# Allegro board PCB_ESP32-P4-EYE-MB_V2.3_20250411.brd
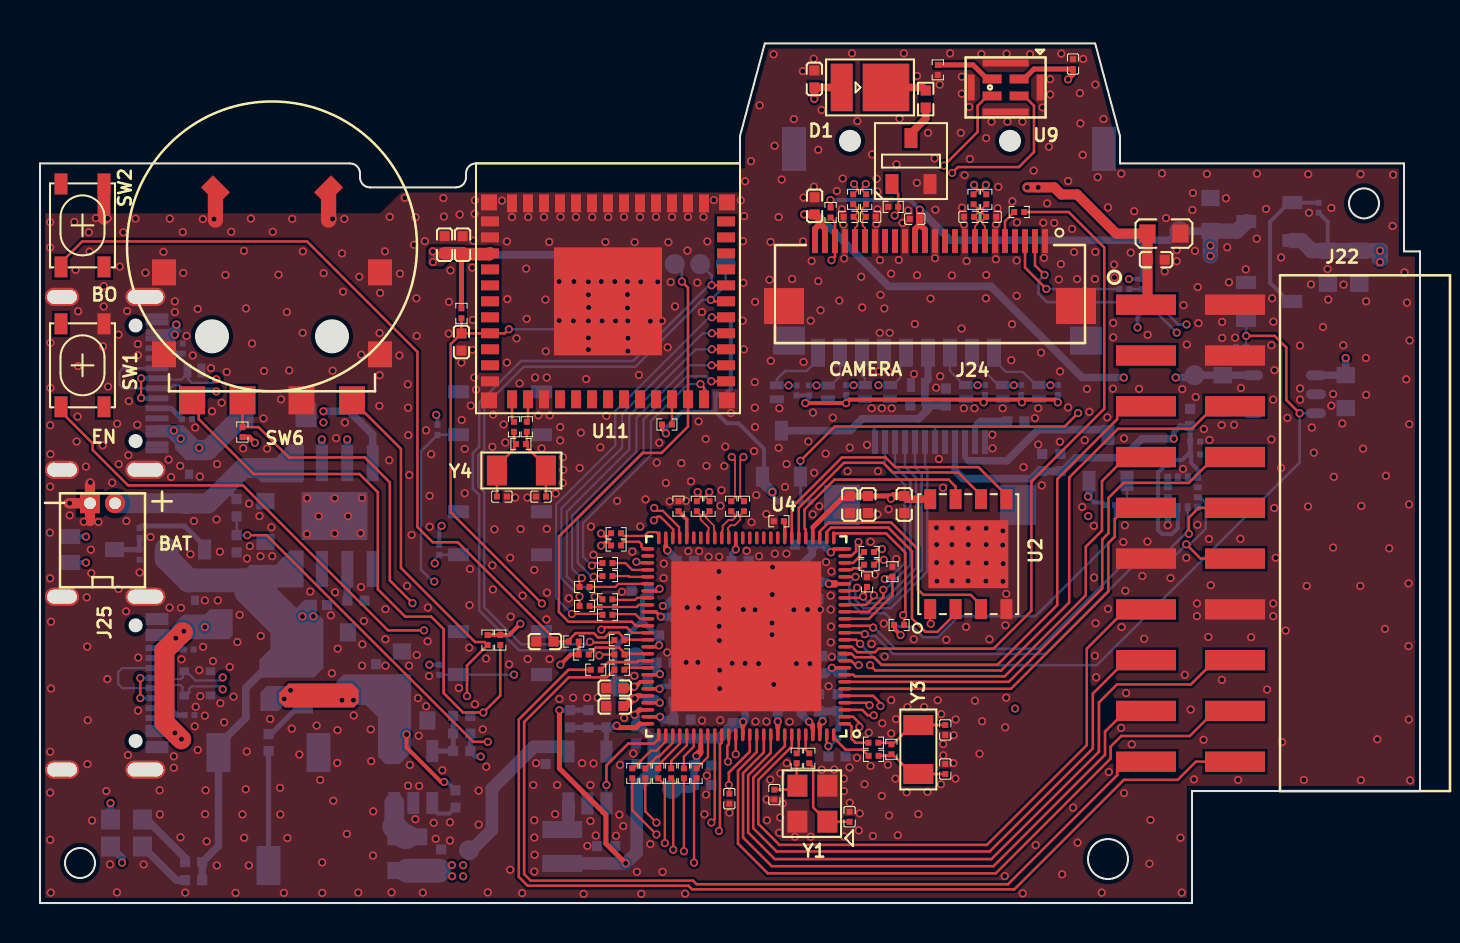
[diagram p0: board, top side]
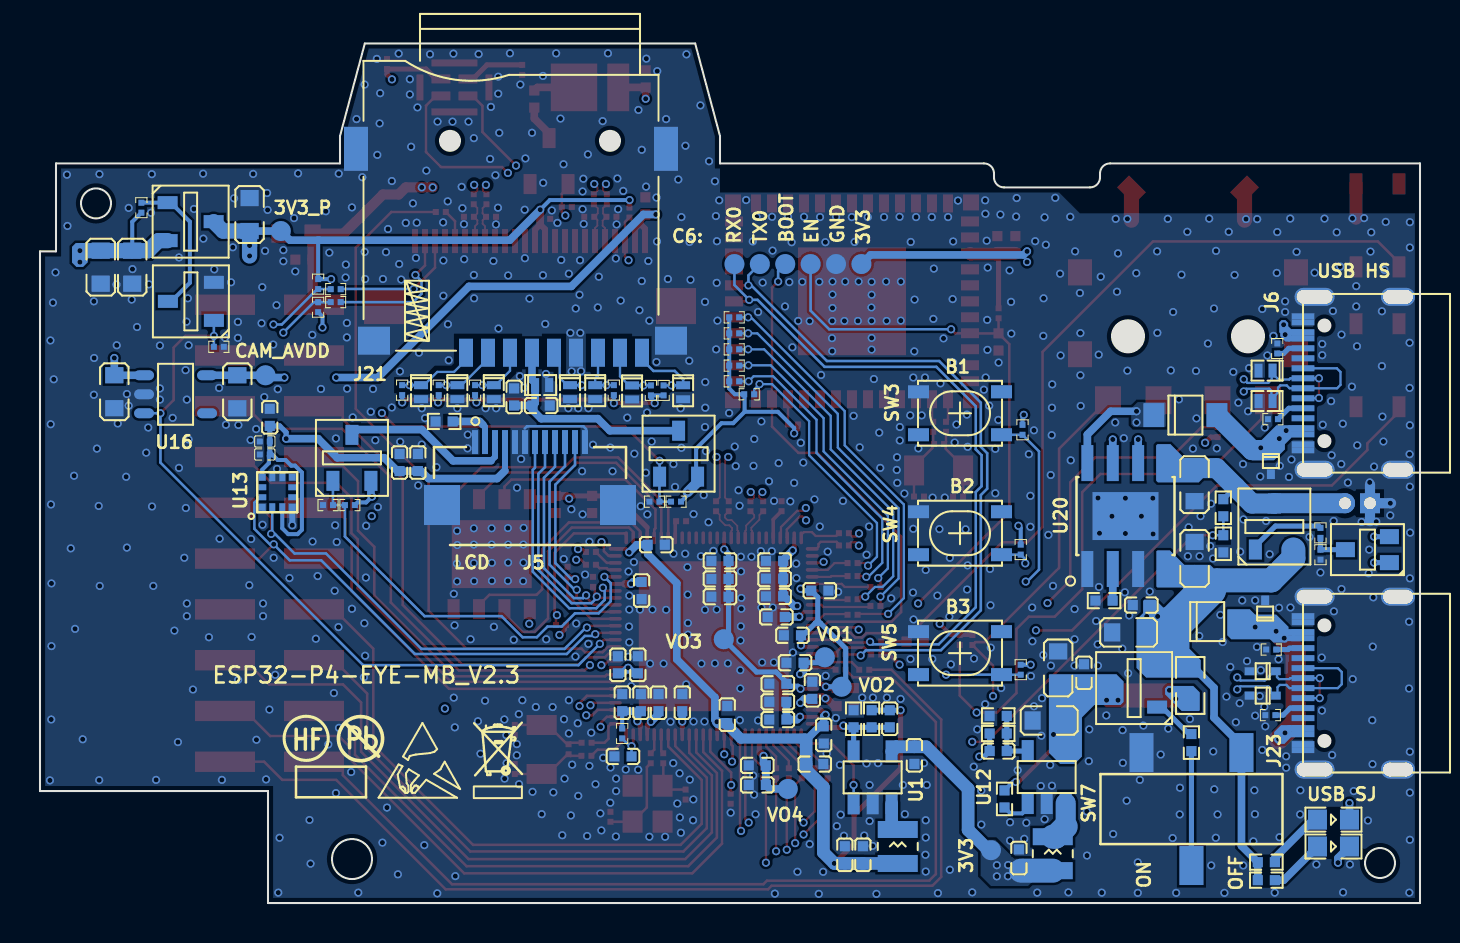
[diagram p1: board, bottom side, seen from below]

Outline 69 x 43 mm; copper layers: TOP, L2_GND1, L3_SIGNAL, L4_GND2, L5_POWER, BOTTOM. Coordinates in mm from the lower left corner of the outline.
Outline path: circle c2,2 r0.75 ; circle c2.5,20 r0.25 ; circle c3.75,20 r0.25 ; circle c4.78,28.89 r0.3 ; circle c4.78,23.11 r0.3 ; circle c4.78,13.89 r0.3 ; circle c4.78,8.11 r0.3 ; circle c8.6,28.35 r0.8 ; circle c14.6,28.35 r0.8 ; circle c40.5,38.13 r0.5 ; circle c48.5,38.13 r0.5 ; circle c53.4,2.2 r1 ; circle c66.2,35 r0.75 ; 0,37 0,0 57.6,0 57.6,5.6 69,5.6 69,32.6 68.2,32.6 68.2,37 54,37 54,38.37 52.76,43 36.24,43 35,38.37 35,37 21.8,37 arc(21.45,36.85) 21.3,36.5 21.3,36.3 arc(21.15,35.95) 20.8,35.8 16.5,35.8 arc(16.15,35.95) 16,36.3 16,36.5 arc(15.85,36.85) 15.5,37 0,37 ; 0.7,30.02 arc(0.4,30.32) 0.7,30.62 1.5,30.62 arc(1.8,30.32) 1.5,30.02 0.7,30.02 ; 0.7,21.38 arc(0.4,21.68) 0.7,21.98 1.5,21.98 arc(1.8,21.68) 1.5,21.38 0.7,21.38 ; 0.7,15.03 arc(0.4,15.32) 0.7,15.62 1.5,15.62 arc(1.8,15.32) 1.5,15.03 0.7,15.03 ; 0.7,6.38 arc(0.4,6.67) 0.7,6.97 1.5,6.97 arc(1.8,6.67) 1.5,6.38 0.7,6.38 ; 4.72,30.02 arc(4.42,30.32) 4.72,30.62 5.82,30.62 arc(6.12,30.32) 5.82,30.02 4.72,30.02 ; 4.72,21.38 arc(4.42,21.68) 4.72,21.98 5.82,21.98 arc(6.12,21.68) 5.82,21.38 4.72,21.38 ; 4.72,15.03 arc(4.42,15.32) 4.72,15.62 5.82,15.62 arc(6.12,15.32) 5.82,15.03 4.72,15.03 ; 4.72,6.38 arc(4.42,6.67) 4.72,6.97 5.82,6.97 arc(6.12,6.67) 5.82,6.38 4.72,6.38

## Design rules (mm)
net group CAM_C: nets CAM_CN CAM_CP
net group CAM_D: nets CAM_DN CAM_DP
net group CSI_CLKN: nets CSI_CLKN CSI_CLKN_A
net group CSI_CLKP: nets CSI_CLKP CSI_CLKP_A
net group CSI_DATA0N: nets CSI_DATA0N CSI_DATA0N_A
net group CSI_DATA0P: nets CSI_DATA0P CSI_DATA0P_A
net group GPIO24: nets GPIO24 USB_SJ_DN
net group GPIO25: nets GPIO25 USB_SJ_DP
net group GPIO27: nets GPIO27 SD2_CMD
net group GPIO28: nets GPIO28 SD2_CLK
net group GPIO29: nets GPIO29 SD2_D0
net group GPIO30: nets GPIO30 SD2_D1
net group GPIO31: nets GPIO31 SD2_D2
net group GPIO32: nets GPIO32 SD2_D3
net group GPIO39: nets GPIO39 SD1_D0
net group GPIO40: nets GPIO40 SD1_D1
net group GPIO41: nets GPIO41 SD1_D2
net group GPIO42: nets GPIO42 SD1_D3
net group GPIO43: nets GPIO43 SD1_CLK
net group GPIO44: nets GPIO44 SD1_CMD
net group USB2: nets USB_DM USB_DP

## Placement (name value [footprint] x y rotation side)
C1  22pF/50V(5%)  [C0201]  40.48 4.31 90 top
C2  1uF/10V(10%)  [C0402]  39.85 7.33 180 bottom
C3  0.1uF/10V(10%)(NC)  [C0402]  25.25 13.08 180 top
C4  22pF/50V(5%)  [C0201]  36.72 5.42 270 top
C5  0.1uF/10V(10%)  [C0402]  43.21 19.94 270 top
C6  4.7uF/6.3V(20%)  [C0402]  25.28 7.39 270 bottom
C7  22pF/50V(5%)(NC)  [C0402]  26.51 9.22 270 bottom
C8  10uF/6.3V(20%)  [C0402]  27.86 2.41 90 bottom
C18  22pF/50V(5%)  [C0201]  45.26 8.66 270 top
C19  22pF/50V(5%)  [C0201]  45.26 6.7 90 top
C20  1uF/10V(10%)  [C0402]  41.39 19.94 270 top
C25  0.1uF/10V(10%)  [C0402]  40.49 19.94 270 top
C47  10uF/6.3V(20%)  [C0402]  38.73 34.88 90 top
C48  0.1uF/10V(10%)  [C0201]  43.74 34.23 180 top
C50  1uF/10V(10%)  [C0402]  28.74 10.75 180 top
C51  1uF/10V(10%)  [C0402]  28.74 9.85 180 top
C52  0.1uF/10V(10%)  [C0402]  38.72 41.23 90 top
C53  10nF/10V(10%)  [C0201]  57.76 22.44 0 bottom
C55  1uF/10V(10%)  [C0402]  32.11 10.97 0 bottom
C56  1uF/10V(10%)  [C0402]  31.25 12.02 0 bottom
C82  10uF/6.3V(20%)  [C0402]  39.89 10.02 90 bottom
C83  0.1uF/10V(10%)  [C0402]  40.11 11.92 90 bottom
C84  0.1uF/10V(10%)  [C0402]  38.96 10.02 90 bottom
C85  0.1uF/10V(10%)  [C0402]  38.07 10.02 90 bottom
C86  0.1uF/10V(10%)  [C0402]  38.19 17.92 180 bottom
C87  10uF/6.3V(20%)  [C0402]  39.11 11.92 90 bottom
C88  0.1uF/10V(10%)  [C0402]  38.92 15.63 270 bottom
C89  10uF/6.3V(20%)  [C0402]  30.26 6.95 180 bottom
C90  0.1uF/10V(10%)  [C0402]  36.89 10.02 90 bottom
C91  1uF/10V(10%)  [C0402]  35 15.32 0 bottom
C92  0.1uF/10V(10%)  [C0402]  35 16.21 0 bottom
C93  10nF/50V(10%)  [C0402]  35 17.11 0 bottom
C94  0.1uF/10V(10%)  [C0402]  34.64 9.42 90 bottom
C95  10uF/6.3V(20%)  [C0402]  32.11 10.07 0 bottom
C96  0.1uF/10V(10%)  [C0402]  32.11 9.18 0 bottom
C97  0.1uF/10V(10%)  [C0402]  32.18 14.31 0 bottom
C98  4.7uF/6.3V(20%)  [C0402]  32.27 15.34 0 bottom
C99  0.1uF/10V(10%)  [C0402]  32.27 16.23 0 bottom
C100  10nF/50V(10%)  [C0402]  32.27 17.12 0 bottom
C101  0.1uF/10V(10%)  [C0402]  33.14 6.89 0 bottom
C102  10uF/6.3V(20%)  [C0402]  33.14 5.91 0 bottom
C103  0.1uF/10V(10%)  [C0402]  30.38 10.64 90 bottom
C104  1uF/10V(10%)  [C0402]  31.38 13.39 0 bottom
C105  0.1uF/10V(10%)  [C0402]  30.01 15.63 180 bottom
C107  0.1uF/10V(10%)  [C0402]  29.81 8.41 270 bottom
C109  10uF/6.3V(20%)  [C0402]  20.23 32.93 90 top
C110  0.1uF/10V(10%)  [C0402]  21.13 32.93 90 top
C111  0.1uF/10V(10%)  [C0402]  21.07 28.07 270 top
C113  10uF/10V(20%)  [C0603]  18.09 11.76 90 bottom
C114  0.1uF/10V(10%)  [C0402]  16.8 11.52 90 bottom
C118  10uF/10V(20%)  [C0603]  14.57 13.54 0 bottom
C119  0.1uF/10V(10%)  [C0402]  13.93 14.9 0 bottom
C120  10uF/10V(20%)  [C0603]  18.54 9.13 0 bottom
C121  22pF/50V(5%)(NC)  [C0402]  21.09 7.6 180 bottom
C122  10uF/6.3V(20%)  [C0402]  20.06 2.25 90 bottom
C138  10uF/10V(20%)  [C0603]  65.28 25.58 270 bottom
C141  10uF/10V(20%)  [C0603]  59.13 25.58 270 bottom
C148  10uF/6.3V(20%)  [C0402]  45.3 25.32 90 bottom
C149  0.1uF/10V(10%)  [C0402]  43.94 24.89 180 bottom
C150  10uF/6.3V(20%)(NC)  [C0402]  51.02 22.04 90 bottom
C151  0.1uF/10V(10%)  [C0402]  50.11 22.04 90 bottom
C152  0.1uF/10V(10%)  [C0201]  51.65 41.97 90 top
C160  0.1uF/10V(10%)  [C0402]  55.8 32.18 0 top
C161  10uF/10V(20%)  [C0603]  56.2 33.49 0 top
C163  TBD  [C0201]  47.55 34.33 0 top
C164  TBD  [C0201]  46.45 34.33 180 top
C165  TBD  [C0201]  41.54 34.33 0 top
C166  TBD  [C0201]  40.43 34.33 180 top
C168  22uF/10V(20%)  [C0603]  11.27 20.93 90 bottom
C169  10uF/10V(20%)  [C0603]  11.27 17.24 270 bottom
C170  22pF/50V(5%)  [C0201]  23.09 20.33 0 top
C171  22pF/50V(5%)  [C0201]  25.05 20.33 180 top
C172  0.1uF/10V(10%)(NC)  [C0201]  34.47 5.22 270 top
C173  10uF/6.3V(20%)  [C0402]  28.76 2.41 90 bottom
C174  10uF/10V(20%)  [C0603]  64.39 31.81 270 bottom
C175  10uF/10V(20%)(NC)  [C0603]  58.52 34.44 90 bottom
C176  0.1uF/10V(10%)  [C0201]  57.76 23.09 0 bottom
C177  2.2uF/10V(20%)  [C0402]  57.51 24.3 90 bottom
C178  10uF/10V(20%)  [C0603]  65.96 31.81 270 bottom
D1  WHITE LED  [LED2835]  41.5 40.8 0 top
D3  LESD8D3.3CAT5G  [SOD882]  43.89 25.91 0 bottom
D4  LESD8D3.3CAT5G  [SOD882]  46.31 25.56 90 bottom
D5  GREEN LED  [LED0603]  4.33 4.17 0 bottom
D6  LESD8D3.3CAT5G  [SOD882]  42.5 25.56 90 bottom
D7  LESD8D3.3CAT5G  [SOD882]  48.13 25.56 90 bottom
D8  LESD8D3.3CAT5G  [SOD882]  49.95 25.56 90 bottom
D10  LESD8D3.3CAT5G  [SOD882]  39.4 25.54 90 bottom
D11  LESD8D3.3CAT5G  [SOD882]  41.24 25.56 90 bottom
D12  DSS24  [SOD123FL]  11.73 24.41 180 bottom
D15  LESD5D5.0CT1G  [SOD523]  7.45 22.11 90 bottom
D16  LESD5D5.0CT1G  [SOD523]  7.87 11.6 180 bottom
D17  LESD5D5.0CT1G  [SOD523]  7.87 10.38 180 bottom
D18  DSS24  [SOD123FL]  10.64 14.08 180 bottom
D19  LESD5D5.0CT1G  [SOD523]  7.74 14.48 270 bottom
D20  ESD7951ST5G  [SOD882]  7.72 26.64 180 bottom
D21  ESD7951ST5G  [SOD882]  7.72 25.11 180 bottom
D22  LESD8D3.3CAT5G  [SOD882]  36.84 25.55 90 bottom
D23  BAT54CW  [SOT323]  2.63 17.68 0 bottom
D25  RED LED  [LED0603]  4.33 2.83 0 bottom
J5  FFC12-0P5-LCD  [FFC12_0P5_AFC24-S12FIC-00]  44.5 23.06 180 bottom
J6  -  [USB_TYPEC_16P_F]  4.78 26 90 bottom
J21  TF_CARD  [TF_CARDA]  45.45 38.13 90 bottom
J22  CON10X2  [CON10X2_2P54_SMT_R]  56.77 18.5 270 top
J23  -  [USB_TYPEC_16P_F]  4.78 11 90 bottom
J24  FPC_24P  [FFC24_0P5_FPC-05FB-24PH20]  44.5 33.11 0 top
J25  CON2X1_1P25  [GH2_1P25_R]  3.12 20 0 top
L1  2.2uH(20%)_2A  [L2520]  26.11 2.83 270 bottom
L5  2.2uH(20%)_2A  [L2520]  18.36 2.47 270 bottom
Q1  LBSS138LT1G  [SOT23-3]  61.46 30.1 0 bottom
Q2  AO3401A  [SOT23-3]  53.4 22.27 90 bottom
Q4  SI2302  [SOT23-3]  43.55 37.12 90 top
Q6  AO3401A  [SOT23-3]  7.28 18.83 90 bottom
Q8  AO3401A  [SOT23-3]  37.07 22.48 90 bottom
Q9  AO3401A  [SOT23-3]  14.29 10.75 0 bottom
Q10  AO3401A  [SOT23-3]  61.47 34.09 180 bottom
R1  0(1%)  [R0201]  38.46 7.24 270 top
R2  10K(1%)  [R0201]  39.89 8.48 90 bottom
R3  10K(1%)  [R0201]  27.19 12.43 0 top
R4  10K(1%)  [R0201]  26.69 13.08 0 top
R5  0(1%)  [R0201]  37.83 7.24 270 top
R7  10K(1%)  [R0201]  42.95 13.91 180 top
R8  499K(1%)(NC)  [R0402]  27.42 9.22 270 bottom
R9  499K(1%)(NC)  [R0402]  28.32 9.22 90 bottom
R10  2K(1%)  [R0402]  15.8 15.13 0 bottom
R15  1M(1%)  [R0402]  9.83 19.77 90 bottom
R16  332K(1%)  [R0402]  9.83 17.97 270 bottom
R17  51K(1%)  [R0201]  47.25 25.66 90 bottom
R23  0(1%)  [R0201]  41.45 17.56 0 top
R24  0(1%)  [R0201]  47.31 35.2 90 top
R25  0(1%)  [R0201]  46.68 35.2 90 top
R26  0(1%)  [R0201]  40.66 35.2 90 top
R27  0(1%)  [R0201]  41.31 35.2 90 top
R58  10M(1%)(NC)  [R0201]  42.57 7.69 90 top
R59  0(1%)  [R0201]  41.67 8.02 0 top
R61  0(1%)  [R0201]  41.68 7.36 0 top
R67  10K(1%)  [R0201]  39.53 34.54 270 top
R72  3.9(1%)  [R0402]  44.28 40.22 270 top
R73  10K(1%)  [R0201]  42.66 34.83 180 top
R79  10K(1%)(NC)  [R0201]  54.6 19.91 0 bottom
R102  0(1%)  [R0201]  32.83 6.49 270 top
R103  0(1%)  [R0201]  32.19 6.49 270 top
R104  33(1%)  [R0201]  28.8 18.5 180 top
R105  33(1%)  [R0201]  28.8 17.89 180 top
R107  0(1%)  [R0201]  31.56 6.49 270 top
R108  0(1%)  [R0201]  30.91 6.49 270 top
R110  0(1%)  [R0201]  30.26 6.49 270 top
R118  0(1%)  [R0201]  28.97 11.67 180 top
R122  0(1%)  [R0201]  29.62 6.49 270 top
R128  51K(1%)  [R0201]  34.29 29.3 180 bottom
R129  51K(1%)  [R0201]  34.29 28.5 180 bottom
R130  51K(1%)  [R0201]  34.29 27.7 180 bottom
R131  51K(1%)  [R0201]  34.29 26.89 180 bottom
R132  51K(1%)  [R0201]  34.29 26.1 180 bottom
R133  51K(1%)  [R0201]  33.54 25.45 180 bottom
R134  100K(1%)  [R0201]  21.07 29.5 90 top
R135  10K(1%)  [R0201]  31.35 23.94 180 top
R142  5.1K(1%)  [R0201]  7.35 24.21 180 bottom
R143  5.1K(1%)  [R0201]  7.14 27.74 270 bottom
R145  10K(1%)  [R0402]  20.77 5.21 270 bottom
R146  100K(1%)  [R0402]  21.09 8.48 180 bottom
R148  22.1K(1%)  [R0402]  21.09 9.36 0 bottom
R202  4.02K(1%)  [R0201]  36.94 19.1 180 top
R203  4.02K(1%)  [R0201]  31.92 19.85 90 top
R230  10K(1%)  [R0201]  63.93 34.79 270 bottom
R231  51K(1%)  [R0201]  49.06 25.66 90 bottom
R232  51K(1%)  [R0201]  40.31 25.66 90 bottom
R233  51K(1%)  [R0201]  38.45 25.65 90 bottom
R234  51K(1%)  [R0201]  50.89 25.66 90 bottom
R238  10K(1%)(NC)  [R0201]  42.62 16.57 90 top
R241  10K(1%)(NC)  [R0201]  41.35 16.07 90 top
R243  10(1%)  [R0402]  48.79 24.09 0 bottom
R246  10K(1%)  [R0201]  44.89 41.68 90 top
R250  0(1%)  [R0201]  28.97 12.43 180 top
R255  0(1%)  [R0201]  41.45 16.93 0 top
R259  0(1%)  [R0201]  27.79 11.67 180 top
R262  10K(1%)  [R0201]  19.88 23.67 90 bottom
R263  10K(1%)  [R0201]  19.96 17.68 90 bottom
R264  10K(1%)  [R0201]  19.96 11.67 90 bottom
R268  5.1K(1%)  [R0201]  7.48 9.4 180 bottom
R269  5.1K(1%)  [R0201]  7.44 12.68 180 bottom
R272  2.2K(1%)  [R0201]  55.09 29.81 270 bottom
R273  2.2K(1%)  [R0201]  55.09 30.96 90 bottom
R274  0(1%)  [R0201]  27.23 14.86 180 top
R275  0(1%)  [R0201]  28.37 15.19 180 top
R276  0(1%)  [R0201]  27.23 15.81 180 top
R277  0(1%)  [R0201]  28.37 16.36 180 top
R278  0(1%)  [R0201]  28.37 17.01 180 top
R279  0(1%)  [R0201]  28.37 14.42 180 top
R280  51K(1%)  [R0201]  37.82 25.65 90 bottom
R283  0(1%)  [R0201]  32.84 19.85 90 top
R284  0(1%)  [R0201]  33.48 19.85 90 top
R285  0(1%)  [R0201]  34.56 19.85 90 top
R286  0(1%)  [R0201]  35.2 19.85 90 top
R288  100K(1%)  [R0201]  4.98 17.42 270 bottom
R289  100K(1%)  [R0201]  4.98 18.52 90 bottom
R290  5.1K(1%)  [R0402]  7.68 1.14 0 bottom
R291  5.1K(1%)  [R0402]  7.68 2.04 0 bottom
R292  10K(1%)  [R0201]  23.01 13.16 90 top
R293  10K(1%)  [R0201]  22.38 13.16 90 top
R295  10K(1%)  [R0201]  10.12 23.56 270 top
R297  10M(1%)(NC)  [R0201]  24.05 22.96 0 top
R298  0(1%)  [R0201]  23.7 23.82 270 top
R299  0(1%)  [R0201]  24.34 23.83 270 top
R300  0(1%)  [R0201]  28.97 13.16 180 top
R302  0(1%)  [R0201]  54.22 30.06 0 bottom
R303  0(1%)  [R0201]  54.22 30.71 0 bottom
R304  0(1%)  [R0201]  48.96 34.57 180 top
R306  10K(1%)  [R0201]  53.51 19.91 0 bottom
R307  100K(1%)  [R0402]  11.43 8.03 270 bottom
R308  10K(1%)(NC)  [R0201]  38.28 20.08 180 bottom
R309  10K(1%)  [R0201]  37.2 20.08 180 bottom
R310  10K(1%)(NC)  [R0201]  60.06 27.83 0 bottom
R311  0(1%)(NC)  [R0603]  11.49 10.88 90 bottom
SW1  SW_SP_4P  [SW4-4P2X3P2X2P5-SMT]  2.12 26.9 270 top
SW2  SW_SP_4P  [SW4-4P2X3P2X2P5-SMT]  2.12 33.9 270 top
SW3  SW_SP_4P  [SW4-4P2X3P2X2P5-SMT]  23 24.5 180 bottom
SW4  SW_SP_4P  [SW4-4P2X3P2X2P5-SMT]  23 18.5 180 bottom
SW5  SW_SP_4P  [SW4-4P2X3P2X2P5-SMT]  23 12.5 180 bottom
SW6  -  [SIQ-02FVS3]  11.6 32.85 0 top
SW7  K3-1235S-F1  [SW3-9P1X3P5X5P5-SMT]  11.43 4.7 180 bottom
TP24  TESTPOINT  [TPC1]  28.92 10.82 180 bottom
TP25  TESTPOINT  [TPC1]  31.61 5.71 180 bottom
TP26  TESTPOINT  [TPC1]  29.76 12.29 180 bottom
TP27  TESTPOINT  [TPC1]  34.81 13.2 180 bottom
TP44  TESTPOINT  [TPC1]  30.47 31.97 0 bottom
TP45  TESTPOINT  [TPC1]  31.74 31.97 0 bottom
TP46  TESTPOINT  [TPC1]  34.28 31.97 90 bottom
TP47  TESTPOINT  [TPC1]  33.01 31.97 90 bottom
TP48  TESTPOINT  [TPC1]  29.2 31.97 90 bottom
TP49  TESTPOINT  [TPC1]  21.45 2.64 0 bottom
TP51  TESTPOINT  [TPC1]  57.72 26.4 0 bottom
TP52  TESTPOINT  [TPC1]  56.96 33.62 270 bottom
TP53  TESTPOINT  [TPC1]  27.93 31.97 180 bottom
U1  TLV62569  [SOT23_0P95_2P6]  27.37 6.28 90 bottom
U2  FLASH  [WSON8_1P27_6X5_E4X3P4]  46.41 17.45 90 top
U4  ESP32-P4  [QFN104_0P35_10_E7P5_A]  35.31 13.34 180 top
U9  MSM261D  [OCLGA-8]  48.28 40.8 90 top
U11  -  [ESP32-C6-MINI-1U]  21.8 24.5 0 top
U12  TLV62569  [SOT23_0P95_2P6]  18.67 6.3 90 bottom
U13  QMA6100P  [LGA12_0P5_2]  57.14 20.55 90 bottom
U16  ME6211C33M5G-N  [SOT23-5]  62.22 25.45 180 bottom
U20  AP5056  [SOP8_1P27_4P9X3P9_E3P3X2P4]  14.73 19.36 90 bottom
Y1  40MHz  [XTAL3225]  38.62 4.97 90 top
Y3  32.768KHz  [XTAL3215_2P]  43.92 7.68 270 top
Y4  32.768KHz  [XTAL3215_2P]  24.07 21.64 180 top

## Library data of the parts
C1-C5 C7 C18 C19 C25 C47 C48 C50-C53 C55 C56 C83-C86 C88 C90 C92 C94 C96 C97 C99 C101 C103 C105 C107 C109-C111 C113 C114 C118 C119 C121 C138 C141 C148-C151 C160 C161 C163-C166 C170-C172 C174-C178 = CAPACITOR
C6 C8 C20 C82 C87 C89 C91 C93 C95 C98 C100 C102 C104 C120 C122 C173 = CAP
C152 C168 C169 = CAP NP
D1 = DIODE_LIGHT
D3 D4 D6-D8 D10 D11 D15-D17 D19-D22 = DIODE_BI_DIR
D5 D25 = LED_1
D12 D18 = DIODE_S
D23 = BAT54C_0
J5 = FFC12-0P5-LCD_3
J6 J23 = USB_TYPEC_16P_F
J21 = TF_SD_SOCKET
J22 = CON10X2
J24 = FPC_24P
J25 = CON2X1
L1 L5 = INDUCTOR
Q1 = MOSFET_EN_DGS_0
Q2 Q8 Q10 = PMOS
Q4 = NMOS
Q6 Q9 = PMOS_0
R1-R5 R7-R9 R17 R23-R27 R58 R59 R61 R67 R72 R73 R79 R118 R128-R135 R142 R143 R145 R146 R148 R202 R203 R230-R234 R238 R241 R243 R250 R255 R259 R262-R264 R268 R269 R272 R273 R280 R292 R293 R295 R297-R300 R302-R304 R306 R308-R311 = RESISTOR
R10 R15 R16 R246 R288-R291 R307 = RESISTOR_0
R102 R103 R107 R108 R110 R122 R274-R279 R283-R286 = RESISTOR: signal model: RESISTOR_R0201_0(1%)_0(1%)
R104 R105 = RESISTOR: signal model: RESISTOR_R0201_33(1%)_33(1%)
SW1-SW5 = SW_SP_4P
SW6 = Encoder
SW7 = SS-12D10L3
TP24-TP27 TP44-TP49 TP51-TP53 = TESTPOINT
U1 U12 = TLV62565
U2 = FLASH_EPAD
U4 = ESP32-P4_QFN104_ECO1_0
U9 = NSM0418DT
U11 = ESP32-C6-MINI-1
U13 = QMA7981_0
U16 = LDO_SOT23-5_3
U20 = AP5056
Y1 = XTAL
Y3 Y4 = XTAL_2P

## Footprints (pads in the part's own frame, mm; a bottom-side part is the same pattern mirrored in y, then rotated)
C0201
  rect 0.3x0.3 smd: 1(-0.25,0) 2(0.25,0)
C0402
  rect 0.508x0.508 smd: 1(-0.429,0) 2(0.429,0)
C0603
  rect 0.813x0.914 smd: 1(-0.826,0) 2(0.826,0)
CON10X2_2P54_SMT_R
  rect 1.02x3 smd: 1(-11.43,-1.475) 2(-11.43,2.975) 3(-8.89,-1.475) 4(-8.89,2.975) 5(-6.35,-1.475) 6(-6.35,2.975) 7(-3.81,-1.475) 8(-3.81,2.975) 9(-1.27,-1.475) 10(-1.27,2.975) 11(1.27,-1.475) 12(1.27,2.975) 13(3.81,-1.475) 14(3.81,2.975) 15(6.35,-1.475) 16(6.35,2.975) 17(8.89,-1.475) 18(8.89,2.975) 19(11.43,-1.475) 20(11.43,2.975)
ESP32-C6-MINI-1U
  rect 0.9x0.5 smd: 1(0.7,9.6) 2(0.7,8.8) 3(0.7,8) 4(0.7,7.2) 5(0.7,6.4) 6(0.7,5.6) 7(0.7,4.8) 8(0.7,4) 9(0.7,3.2) 10(0.7,2.4) 11(0.7,1.6) 25(12.5,1.6) 26(12.5,2.4) 27(12.5,3.2) 28(12.5,4) 29(12.5,4.8) 30(12.5,5.6) 31(12.5,6.4) 32(12.5,7.2) 33(12.5,8) 34(12.5,8.8) 35(12.5,9.6)
  rect 0.5x0.9 smd: 12(1.8,0.7) 13(2.6,0.7) 14(3.4,0.7) 15(4.2,0.7) 16(5,0.7) 17(5.8,0.7) 18(6.6,0.7) 19(7.4,0.7) 20(8.2,0.7) 21(9,0.7) 22(9.8,0.7) 23(10.6,0.7) 24(11.4,0.7) 36(11.4,10.5) 37(10.6,10.5) 38(9.8,10.5) 39(9,10.5) 40(8.2,10.5) 41(7.4,10.5) 42(6.6,10.5) 43(5.8,10.5) 44(5,10.5) 45(4.2,10.5) 46(3.4,10.5) 47(2.6,10.5) 48(1.8,10.5)
  rect 5.4x5.4 smd: 49(6.6,5.6)
  rect 0.8x0.8 smd: 50(12.55,10.55) 51(12.55,0.65) 52(0.65,0.65) 53(0.65,10.55)
FFC12_0P5_AFC24-S12FIC-00
  rect 0.3x1.2 smd: 1(-2.75,0) 2(-2.25,0) 3(-1.75,0) 4(-1.25,0) 5(-0.75,0) 6(-0.25,0) 7(0.25,0) 8(0.75,0) 9(1.25,0) 10(1.75,0) 11(2.25,0) 12(2.75,0)
  rect 1.8x2 smd: 13(-4.4,-3.15) 14(4.4,-3.15)
FFC24_0P5_FPC-05FB-24PH20
  rect 0.3x1.2 smd: 1(5.75,0) 2(5.25,0) 3(4.75,0) 4(4.25,0) 5(3.75,0) 6(3.25,0) 7(2.75,0) 8(2.25,0) 9(1.75,0) 10(1.25,0) 11(0.75,0) 12(0.25,0) 13(-0.25,0) 14(-0.75,0) 15(-1.25,0) 16(-1.75,0) 17(-2.25,0) 18(-2.75,0) 19(-3.25,0) 20(-3.75,0) 21(-4.25,0) 22(-4.75,0) 23(-5.25,0) 24(-5.75,0)
  rect 2x1.8 smd: 25(-7.3,-3.25) 26(7.3,-3.25)
GH2_1P25_R
  rect 1x1 hole 0.5: 1(-0.625,0)
  round 1 hole 0.5: 2(0.625,0)
L2520
  rect 0.85x2 smd: 1(-0.85,0) 2(0.85,0)
LED0603
  rect 0.95x1 smd: 1(0.8,0) 2(-0.8,0)
LED2835
  rect 1.1x2.38 smd: 1(-1.415,0)
  rect 2.33x2.38 smd: 2(0.8,0)
LGA12_0P5_2
  rect 0.35x0.35 smd: 1(-0.75,0.75) 4(-0.75,-0.75) 7(0.75,-0.75) 10(0.75,0.75)
  rect 0.4x0.3 smd: 2(-0.75,0.25) 3(-0.75,-0.25) 8(0.75,-0.25) 9(0.75,0.25)
  rect 0.3x0.4 smd: 5(-0.25,-0.75) 6(0.25,-0.75) 11(0.25,0.75) 12(-0.25,0.75)
OCLGA-8
  rect 0.45x0.95 smd: 1(0.425,-0.675) 2(0.425,0.675) 3(-0.425,0.675) 4(-0.425,-0.675)
  rect 1.3x0.35 smd: 5(0,-1.725) 7(0,1.725)
  rect 0.35x2.3 smd: 6(-1.225,0) 8(1.225,0)
QFN104_0P35_10_E7P5_A
  oval 0.65x0.18 smd: 1(-4.925,4.375) 2(-4.925,4.025) 3(-4.925,3.675) 4(-4.925,3.325) 5(-4.925,2.975) 6(-4.925,2.625) 7(-4.925,2.275) 8(-4.925,1.925) 9(-4.925,1.575) 10(-4.925,1.225) 11(-4.925,0.875) 12(-4.925,0.525) 13(-4.925,0.175) 14(-4.925,-0.175) 15(-4.925,-0.525) 16(-4.925,-0.875) 17(-4.925,-1.225) 18(-4.925,-1.575) 19(-4.925,-1.925) 20(-4.925,-2.275) 21(-4.925,-2.625) 22(-4.925,-2.975) 23(-4.925,-3.325) 24(-4.925,-3.675) 25(-4.925,-4.025) 26(-4.925,-4.375) 53(4.925,-4.375) 54(4.925,-4.025) 55(4.925,-3.675) 56(4.925,-3.325) 57(4.925,-2.975) 58(4.925,-2.625) 59(4.925,-2.275) 60(4.925,-1.925) 61(4.925,-1.575) 62(4.925,-1.225) 63(4.925,-0.875) 64(4.925,-0.525) 65(4.925,-0.175) 66(4.925,0.175) 67(4.925,0.525) 68(4.925,0.875) 69(4.925,1.225) 70(4.925,1.575) 71(4.925,1.925) 72(4.925,2.275) 73(4.925,2.625) 74(4.925,2.975) 75(4.925,3.325) 76(4.925,3.675) 77(4.925,4.025) 78(4.925,4.375)
  oval 0.18x0.65 smd: 27(-4.375,-4.925) 28(-4.025,-4.925) 29(-3.675,-4.925) 30(-3.325,-4.925) 31(-2.975,-4.925) 32(-2.625,-4.925) 33(-2.275,-4.925) 34(-1.925,-4.925) 35(-1.575,-4.925) 36(-1.225,-4.925) 37(-0.875,-4.925) 38(-0.525,-4.925) 39(-0.175,-4.925) 40(0.175,-4.925) 41(0.525,-4.925) 42(0.875,-4.925) 43(1.225,-4.925) 44(1.575,-4.925) 45(1.925,-4.925) 46(2.275,-4.925) 47(2.625,-4.925) 48(2.975,-4.925) 49(3.325,-4.925) 50(3.675,-4.925) 51(4.025,-4.925) 52(4.375,-4.925) 79(4.375,4.925) 80(4.025,4.925) 81(3.675,4.925) 82(3.325,4.925) 83(2.975,4.925) 84(2.625,4.925) 85(2.275,4.925) 86(1.925,4.925) 87(1.575,4.925) 88(1.225,4.925) 89(0.875,4.925) 90(0.525,4.925) 91(0.175,4.925) 92(-0.175,4.925) 93(-0.525,4.925) 94(-0.875,4.925) 95(-1.225,4.925) 96(-1.575,4.925) 97(-1.925,4.925) 98(-2.275,4.925) 99(-2.625,4.925) 100(-2.975,4.925) 101(-3.325,4.925) 102(-3.675,4.925) 103(-4.025,4.925) 104(-4.375,4.925)
  rect 7.5x7.5 smd: 105(0,0)
R0201
  rect 0.3x0.3 smd: 1(-0.25,0) 2(0.25,0)
R0402
  rect 0.508x0.508 smd: 1(-0.429,0) 2(0.429,0)
R0603
  rect 0.813x0.914 smd: 1(-0.826,0) 2(0.826,0)
SIQ-02FVS3
  round 1.6 hole 1.6 unplated: (-3,-4.5) (3,-4.5)
  rect 1.3x1.4 smd: 1(-4,-7.7) 2(-1.475,-7.7) 3(1.475,-7.7) 4(4,-7.7)
  rect 1.2x1.3 smd: 5(5.4,-5.4) 6(-5.4,-5.4) 7(-5.4,-1.3) 8(5.4,-1.3)
  rect 0.85x1.2 smd rot 45: 9(-2.828,2.828)
  rect 0.85x1.2 smd rot 135: 10(2.828,2.828)
SOD123FL
  rect 1.05x1.2 smd: 1(1.575,0) 2(-1.575,0)
SOD523
  rect 0.48x0.4 smd: 1(-0.66,0) 2(0.66,0)
SOD882
  rect 0.4x0.7 smd: 1(-0.35,0) 2(0.35,0)
SOP8_1P27_4P9X3P9_E3P3X2P4
  rect 1.8x0.6 smd: 1(-2.65,1.905) 2(-2.65,0.635) 3(-2.65,-0.635) 4(-2.65,-1.905) 5(2.65,-1.905) 6(2.65,-0.635) 7(2.65,0.635) 8(2.65,1.905)
  rect 2.4x3.3 smd: 9(0,0)
SOT23-3
  rect 1x0.65 smd: 1(-1.15,0.95) 2(-1.15,-0.95) 3(1.15,0)
SOT23-5
  oval 1x0.5 smd: 1(-1.575,0.95) 2(-1.575,0) 3(-1.575,-0.95) 4(1.575,-0.95) 5(1.575,0.95)
SOT23_0P95_2P6
  rect 1.1x0.6 smd: 1(-1.3,0.95) 2(-1.3,0) 3(-1.3,-0.95) 4(1.3,-0.95) 5(1.3,0.95)
SOT323
  rect 0.95x0.75 smd: 1(-1.1,0.65) 2(-1.1,-0.65) 3(1.1,0)
SW3-9P1X3P5X5P5-SMT
  rect 1.2x1.95 smd: 1(-2.5,2.825) 2(0,-2.825) 3(2.5,2.825)
SW4-4P2X3P2X2P5-SMT
  rect 1.05x0.65 smd: 1(-2.075,1.075) 2(-2.075,-1.075) 3(2.075,-1.075) 4(2.075,1.075)
TF_CARDA
  round 1 hole 1 unplated: (0,-4.95) (0,3.05)
  rect 1.4x0.7 smd: 1(-10.6,2.25) 2(-10.6,1.15) 3(-10.6,0.05) 4(-10.6,-1.05) 5(-10.6,-2.15) 6(-10.6,-3.25) 7(-10.6,-4.35) 8(-10.6,-5.45) 9(-10.6,-6.55)
  rect 1.4x1.6 smd: 10(-10,-8) 12(-10,6.85)
  rect 2.2x1.2 smd: 11(-0.4,-7.75) 13(-0.4,7.75)
TPC1
  round 1 smd: 1(0,0)
USB_TYPEC_16P_F
  round 0.6 hole 0.6 unplated: (-2.89,0) (2.89,0)
  rect 0.3x1.14 smd: 1(-3.35,1.07) 2(-3.05,1.07) 3(-2.55,1.07) 4(-2.25,1.07) 5(-1.75,1.07) 6(-1.25,1.07) 7(-0.75,1.07) 8(-0.25,1.07) 9(0.25,1.07) 10(0.75,1.07) 11(1.25,1.07) 12(1.75,1.07) 13(2.25,1.07) 14(2.55,1.07) 15(3.05,1.07) 16(3.35,1.07)
  oval 0.9x1.7 hole 0.6x1.4: 17(-4.325,-3.68) 20(4.325,-3.68)
  oval 0.9x2 hole 0.6x1.7: 18(-4.325,0.49) 19(4.325,0.49)
WSON8_1P27_6X5_E4X3P4
  rect 1x0.6 smd: 1(-2.75,1.905) 2(-2.75,0.635) 3(-2.75,-0.635) 4(-2.75,-1.905) 5(2.75,-1.905) 6(2.75,-0.635) 7(2.75,0.635) 8(2.75,1.905)
  rect 3.4x4 smd: 9(0,0)
XTAL3215_2P
  rect 1x1.5 smd: 1(-1.225,0) 2(1.225,0)
XTAL3225
  rect 1.1x1 smd: 1(-0.9,-0.75) 2(0.9,-0.75) 3(0.9,0.75) 4(-0.9,0.75)

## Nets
3V3_PERI: C48.1 C52.1 C53.1 C150.1 C151.1 C152.1 C175.1 C176.1 C177.1 D1.1(ANODE) J5.4(VDD) J24.13 J24.14 Q10.3(D) R67.1 R272.2 R273.2 TP52.1 U9.1(VDD) U13.3(VDD_IO) U13.10(SEN_B)
GND: C1.2 C2.1 C3.2 C4.2 C5.2 C6.2 C8.2 C18.2 C19.2 C20.2 C25.2 C47.2 C48.2 C50.2 C51.2 C52.2 C53.2 C55.2 C56.2 C82.2 C83.2 C84.2 C85.2 C86.2 C87.2 C88.2 C89.2 C90.2 C91.2 C92.2 C93.2 C94.2 C95.2 C96.2 C97.2 C98.2 C99.2 C100.2 C101.2 C102.2 C103.2 C104.2 C105.2 C107.2 C109.2 C110.2 C111.2 C113.2 C114.2 C118.2 C119.2 C120.2 C122.2 C138.2 C141.2 C148.2 C149.2 C150.2 C151.2 C152.2 C160.2 C161.2 C163.2 C164.2 C165.2 C166.2 C168.1 C169.1 C170.2 C171.2 C172.2 C173.2 C174.2 C175.2 C176.2 C177.2 C178.2 D3.1 D4.1 D6.1 D7.1 D8.1 D10.1 D11.1 D15.1 D16.1 D17.1 D19.1 D20.1 D21.1 D22.1 J5.1(GND1) J5.5(GND2) J5.6(GND3) J5.12(GND4) J5.13(GND5) J5.14(GND6) J6.1(A1_G) J6.2(B12_G) J6.15(B1_G) J6.16(A12_G) J6.17(E_G1) J6.18(E_G2) J6.19(E_G3) J6.20(E_G4) J21.6(VSS) J21.10(G1) J21.11(G2) J21.12(G3) J21.13(G4) J22.2 J22.4 J22.11 J22.14 J23.1(A1_G) J23.2(B12_G) J23.15(B1_G) J23.16(A12_G) J23.17(E_G1) J23.18(E_G2) J23.19(E_G3) J23.20(E_G4) J24.1 J24.6 J24.9 J24.12 J24.15 J24.18 J24.21 J24.25 J24.26 J25.1 Q1.2(S) Q4.2(S) R9.2 R10.2 R16.2 R73.2 R79.2 R142.1 R143.1 R148.2 R202.2 R203.2 R238.2 R241.2 R243.2 R246.1 R268.1 R269.1 R288.2 R308.1 R310.1 SW1.1 SW2.1 SW3.1 SW4.1 SW5.1 SW6.3(C) SW6.5(GND1) SW6.6(GND2) SW6.7(GND3) SW6.8(GND4) SW6.9(GND5) SW6.10(GND6) SW7.1 TP48.1 U1.2(GND) U2.4(GND) U2.9(EPAD) U4.105(GND) U9.5(GND1) U9.6(GND2) U9.7(GND3) U9.8(GND4) U11.1(GND#1) U11.2(GND#2) U11.11(GND#11) U11.14(GND#14) U11.36(GND#36) U11.37(GND#37) U11.38(GND#38) U11.39(GND#39) U11.40(GND#40) U11.41(GND#41) U11.42(GND#42) U11.43(GND#43) U11.44(GND#44) U11.45(GND#45) U11.46(GND#46) U11.47(GND#47) U11.48(GND#48) U11.49(EPAD) U11.50(GND#50) U11.51(GND#51) U11.52(GND#52) U11.53(GND#53) U12.2(GND) U13.1(AD0) U13.4(RES_V1) U13.8(GND_IO) U13.9(GND) U16.2(GND) U20.1(TEMP) U20.3(GND) U20.9(PGND) Y1.2(GND#2) Y1.4(GND#4)
VBAT: C168.2 J25.2 Q6.3(D) R15.2 U20.5(BAT)
VCC_5V: C113.1 C114.1 C120.1 C138.1 C160.1 C161.1 J22.1 Q9.3(D) R145.1 R311.1 U12.4(VIN) U16.1(VIN)
BAT_ADC: C172.1 R15.1 R16.1 U4.92(GPIO49)
BAT_CHRG: D25.2(CATHODE) U20.7(\\C\H\R\G)
BAT_STBY: D5.2(CATHODE) U20.6(\\S\T\D\B\Y)
BUTTON_1: R262.1 SW3.3 U4.3(GPIO3)
BUTTON_2: R263.1 SW4.3 U4.4(GPIO4)
BUTTON_3: R264.1 SW5.3 U4.5(GPIO5)
C6_BOOT: TP45.1 U4.64(GPIO33) U11.23(IO9)
C6_EN: C111.1 R134.1 TP44.1 U4.10(GPIO9) U11.8(EN)
C6_IO0: R298.1 U11.12(IO0)
C6_IO1: R299.1 U11.13(IO1)
C6_IO8: R135.1 U11.22(IO8)
C6_U0RXD: R300.2 TP46.1 U11.30(RXD0)
C6_U0TXD: R250.2 TP47.1 U11.31(TXD0)
CAM_3V3: C47.1 C141.1 J24.23 J24.24 TP51.1 U16.5(OUT)
CAM_CN: C164.1 J24.8 R25.1
CAM_CP: C163.1 J24.7 R24.1
CAM_DN: C165.1 J24.19 R27.1
CAM_DP: C166.1 J24.20 R26.1
CAM_I2C_SCL: J24.3 R303.1
CAM_I2C_SDA: J24.2 R302.1
CAM_MCLK: J24.5 R304.2
CAM_RESET: J24.22 R67.2 U4.55(GPIO26)
CNN_GPIO6: J22.9 U4.6(GPIO6)
CNN_GPIO7: J22.8 U4.7(GPIO7)
CNN_GPIO8: J22.7 U4.8(GPIO8)
CNN_GPIO10: J22.5 U4.11(GPIO10)
CNN_GPIO34: J22.6 U4.65(GPIO34)
CNN_GPIO37: J22.20 R259.2
CNN_GPIO38: J22.19 R118.2
CNN_GPIO50: J22.18 U4.93(GPIO50)
CNN_GPIO51: J22.17 U4.94(GPIO51)
CNN_GPIO52: J22.16 U4.95(GPIO52)
CNN_GPIO53: J22.15 U4.97(GPIO53)
CNN_GPIO54: J22.13 U4.98(GPIO54)
CSI_CLKN: R25.2 R283.2
CSI_CLKN_A: R283.1 U4.45(CSI_CLKN)
CSI_CLKP: R24.2 R284.2
CSI_CLKP_A: R284.1 U4.44(CSI_CLKP)
CSI_DATA0N: R27.2 R286.2
CSI_DATA0N_A: R286.1 U4.42(CSI_DATAN0)
CSI_DATA0P: R26.2 R285.2
CSI_DATA0P_A: R285.1 U4.43(CSI_DATAP0)
CSI_REXT: R203.1 U4.48(CSI_REXT)
DSI_REXT: R202.1 U4.34(DSI_REXT)
EN_DCDC: U1.1(EN/PG) U4.79(EN_DCDC)
ENCODER_A: R292.1 SW6.1(A) U4.90(GPIO48)
ENCODER_B: R293.1 SW6.4(B) U4.89(GPIO47)
ENCODER_SW: R295.1 SW6.2(S) U4.2(GPIO2)
ESP_3V3: C6.1 C82.1 C83.1 C84.1 C85.1 C87.1 C88.1 C90.1 C95.1 C96.1 C97.1 C98.1 C99.1 C100.1 C103.1 C109.1 C110.1 C121.1 C122.1 C174.1 C178.1 L5.2 Q2.2(S) Q8.2(S) Q10.2(S) R2.2 R3.1 R4.2 R128.1 R129.1 R130.1 R131.1 R132.1 R133.1 R134.2 R135.2 R146.1 R230.2 R262.2 R263.2 R264.2 R295.2 R306.1 R309.2 TP49.1 TP53.1 U1.4(VIN) U4.9(VDDPST_1) U4.21(VDDPST_2) U4.51(VCCA) U4.62(VDDPST_4) U4.75(VDDPST_LDO) U4.77(VDDPST_DCDC) U4.96(VDDPST_6) U4.101(VDDA) U4.102(VBAT) U11.3(3V3)
ESP_EN: C2.2 R2.1 SW1.3 U4.103(CHIP_PU)
ESP_I2C_SCL: J22.12 R273.1 R303.2 U4.14(GPIO13) U13.12(SCX)
ESP_I2C_SDA: J22.10 R272.1 R302.2 U4.15(GPIO14) U13.2(SDX)
ESP_LDO_VO1: C5.1 C20.1 C25.1 C56.1 R7.2 TP26.1 U2.8(VCC) U4.30(VDDPST_3) U4.71(VFB1/VO1)
ESP_LDO_VO2: C50.1 C104.1 C105.1 TP24.1 U4.59(VDDPST#59) U4.67(VDDPST#67) U4.72(VFB2/VO2)
ESP_LDO_VO3: C55.1 C91.1 C92.1 C93.1 TP27.1 U4.41(VDD_MIPI_DPHY) U4.73(VFB3/VO3)
ESP_LDO_VO4: C51.1 C101.1 C102.1 R17.1 R231.1 R232.1 R233.1 R234.1 R280.1 R292.2 R293.2 TP25.1 U4.74(VFB4/VO4) U4.85(VDDPST_5)
ESP_VDD_HP: C7.1 C8.1 C86.1 C89.1 C94.1 C107.1 C173.1 L1.2 R8.1 U4.26(VDD_HP_0) U4.76(VDD_HP_2) U4.91(VDD_HP_3)
FB_DCDC: C7.2 R8.2 R9.1 U1.5(FB) U4.78(FB_DCDC)
FLASH_CK: U2.6(CLK) U4.32(FLASH_CK)
FLASH_CS: R7.1 U2.1(/CS) U4.27(FLASH_CS)
FLASH_D: U2.5(DI) U4.33(FLASH_D)
FLASH_HD: U2.7(/HOLD) U4.31(FLASH_HOLD)
FLASH_Q: U2.2(DO) U4.28(FLASH_Q)
FLASH_WP: U2.3(/WP) U4.29(FLASH_WP)
GPIO0: R61.1 U4.104(GPIO0)
GPIO1: R59.1 U4.1(GPIO1)
GPIO11: R304.1 U4.12(GPIO11)
GPIO21: R255.1 U4.23(GPIO21)
GPIO22: R23.1 U4.24(GPIO22)
GPIO24: R104.1 U4.52(GPIO24)
GPIO25: R105.1 U4.53(GPIO25)
GPIO27: R278.1 U4.56(GPIO27)
GPIO28: R277.1 U4.57(GPIO28)
GPIO29: R276.1 U4.58(GPIO29)
GPIO30: R275.1 U4.60(GPIO30)
GPIO31: R274.1 U4.61(GPIO31)
GPIO32: R279.1 U4.63(GPIO32)
GPIO35_BOOT: C3.1 R4.1 R300.1 SW2.3 U4.66(GPIO35)
GPIO36: R3.2 R250.1 U4.68(GPIO36)
GPIO37: R259.1 U4.69(GPIO37)
GPIO38: R118.1 U4.70(GPIO38)
GPIO39: R122.1 U4.80(GPIO39)
GPIO40: R110.1 U4.81(GPIO40)
GPIO41: R108.1 U4.82(GPIO41)
GPIO42: R107.1 U4.83(GPIO42)
GPIO43: R103.1 U4.84(GPIO43)
GPIO44: R102.1 U4.86(GPIO44)
LCD_BL: Q2.1(G) R79.1 R306.2 U4.22(GPIO20)
LCD_CS: J5.8(CS) R241.1 U4.19(GPIO18)
LCD_DC: J5.7(RS) U4.20(GPIO19)
LCD_RST: J5.11(RESET) R238.1 U4.16(GPIO15)
LCD_SCLK: J5.9(SCK) U4.18(GPIO17)
LCD_SDA: J5.10(SDA) U4.17(GPIO16)
LED_A: J5.3(LED_A) Q2.3(D)
LED_CTRL: Q4.1(G) R73.1 U4.25(GPIO23)
LED_K: J5.2(LED_K) R243.1
LPI2S_CLK: R23.2 U9.3(CLK)
LPI2S_DAT: R255.2 U9.4(DATA)
PWR_CTRL: Q1.1(G) R310.2 U4.13(GPIO12) U16.3(EN)
SD1_CLK: D6.2 J21.5(CLK) R103.2
SD1_CMD: D4.2 J21.3(CMD) R17.2 R102.2
SD1_D0: D11.2 J21.7(DATA0) R122.2 R232.2
SD1_D1: D10.2 J21.8(DATA1) R110.2 R233.2
SD1_D2: D8.2 J21.1(DATA2) R108.2 R234.2
SD1_D3: D7.2 J21.2(CD/DATA3) R107.2 R231.2
SD1_VDD: C148.1 C149.1 D3.2 J21.4(VDD) Q8.3(D)
SD2_CLK: R132.2 R277.2 U11.25(IO19)
SD2_CMD: R133.2 R278.2 U11.24(IO18)
SD2_D0: R131.2 R276.2 U11.26(IO20)
SD2_D1: R130.2 R275.2 U11.27(IO21)
SD2_D2: R129.2 R274.2 U11.28(IO22)
SD2_D3: R128.2 R279.2 U11.29(IO23)
SD_DET: D22.2 J21.9(CD) R280.2 U4.87(GPIO45)
SD_PWRN: Q8.1(G) R308.2 R309.1 U4.88(GPIO46)
USB_DM: D20.2 J6.7(B7_DN2) J6.9(A7_DN1) U4.49(DM)
USB_DP: D21.2 J6.8(A6_DP1) J6.10(B6_DP2) U4.50(DP)
USB_SJ_DN: D16.2 J23.7(B7_DN2) J23.9(A7_DN1) R104.2
USB_SJ_DP: D17.2 J23.8(A6_DP1) J23.10(B6_DP2) R105.2
VUSB: C118.1 C119.1 C169.2 D12.2(K) D18.2(K) Q6.2(S) Q9.2(S) R290.2 R291.2 R311.2 SW7.3 U20.4(VCC) U20.8(CE)
VUSB1_IN: D18.1(A) D19.2 D23.1 J23.3(A4_VBUS) J23.4(B9_VBUS) J23.13(B4_VBUS) J23.14(A9_VBUS)
VUSB2_IN: D12.1(A) D15.2 D23.2 J6.3(A4_VBUS) J6.4(B9_VBUS) J6.13(B4_VBUS) J6.14(A9_VBUS)
XTAL_N: R5.1 U4.99(XTAL_N)
XTAL_P: R1.1 U4.100(XTAL_P)
N16934509: C1.1 R1.2 Y1.1(XIN)
N16934523: C4.1 R5.2 Y1.3(XOUT)
N18193822: L1.1 U1.3(SW)
N18255493: J6.6(A5_CC1) R142.2
N18255499: J6.12(B5_CC2) R143.2
N18262730: C121.2 R146.2 R148.1 U12.5(FB)
N18262777: R145.2 U12.1(EN/PG)
N18262785: L5.1 U12.3(SW)
N18700058: D1.2(CATHODE) R72.1
N18700064: Q4.3(D) R72.2
N18877972: R246.2 U9.2(L/R)
N18902905: J23.6(A5_CC1) R268.2
N18902911: J23.12(B5_CC2) R269.2
N19010219: D23.3 R288.1 R289.1
N19010303: Q6.1(G) R289.2
N19013156: R10.1 U20.2(PROG)
N19013226: D25.1(ANODE) R290.1
N19013232: D5.1(ANODE) R291.1
N19026853: C19.1 R58.1 R61.2 Y3.2
N19026868: C18.1 R58.2 R59.2 Y3.1
N19027177: C170.1 R297.1 R298.2 Y4.2
N19027184: C171.1 R297.2 R299.2 Y4.1
N19080261: Q9.1(G) R307.1
N19080264: R307.2 SW7.2
N19083043: Q1.3(D) Q10.1(G) R230.1

Pads without a net: J6 5 11; J22 3; J23 5 11; J24 4 10 11 16 17; SW1 2 4; SW2 2 4; SW3 2 4; SW4 2 4; SW5 2 4; U4 35 36 37 38 39 40 46 47 54; U11 4 5 6 7 9 10 15 16 17 18 19 20 21 32 33 34 35; U13 5 6 7 11; U16 4

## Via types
v1: diameter 0.406, hole 0.254, TOP to BOTTOM, 1095 vias

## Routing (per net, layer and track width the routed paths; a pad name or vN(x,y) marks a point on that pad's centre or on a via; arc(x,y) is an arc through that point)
3V3_PERI: length 98.9
  TOP w0.2: R67.1 39.53,35.16 v1(39.52,35.17)
  TOP w0.254: v1(51.4,41.21) 51.65,41.45 C152.1 49.7,41.72 49.2,41.23 U9.1
  TOP w0.3: J24.13 44.25,33.69 43.99,33.95 43.75,33.71 J24.14
  TOP w0.381: D1.1 38.72,40.8 C52.1 v1(38.72,40.23) ; v1(43.99,34.68) C48.1 43.99,33.95
  L3_SIGNAL w0.2: v1(54.44,31.21) 54.44,29.22 v1(54.88,28.79)
  L3_SIGNAL w0.4: v1(58.52,32.37) 58.52,24.88 56.87,23.23 v1(56.69,23.23)
  L5_POWER w0.381: v1(38.72,40.23) 40.42,41.94 50.67,41.94 v1(51.4,41.21) 51.4,36.99 52.97,35.42 55.99,35.42 v1(58.52,32.89)
  BOTTOM w0.2: R272.2 54.88,29.34 v1(54.88,28.79) ; U13.3 56.89,18.75 56.59,18.45 56.12,18.45 55.91,18.67 55.91,21.54 56.25,21.88 56.44,21.88 56.72,22.16 57.11,22.16 57.39,22.44 C53.1 57.56,22.39 57.56,22.01 57.89,21.68 U13.10 ; v1(43.99,34.68) 43.51,35.17 v1(39.52,35.17) ; v1(54.44,31.21) R273.2 55.09,33.15 55.08,33.16
  BOTTOM w0.254: C53.1 C176.1 57.51,23.09 C177.1 57.01,23.87 56.69,23.55 v1(56.69,23.23)
  BOTTOM w0.3: 45.75,21.63 J5.4
  BOTTOM w0.381: v1(43.99,34.68) 45.51,33.16 56.5,33.16 TP52.1 C175.1 ; 45.75,21.63 46.14,21.23 49.57,21.23 49.94,21.61 C151.1 C150.1 51.12,21.61 51.79,22.28 54.14,22.28 55.09,23.23 v1(56.69,23.23)
  BOTTOM w0.762: Q10.3 59.85,33.62 C175.1 v1(58.52,32.89) v1(58.52,32.37)
GND: length 26.8
  TOP w0.508: J25.1 v1(1.48,20) 1.44,20 ; J25.1 2.5,19.11 ; J25.1 2.5,20.96
  TOP w0.635: SW2.1 3.2,34.25
  TOP w0.762: SW6.9 8.77,34.17 ; SW6.10 14.43,34.16
  L2_GND1 w0.508: J25.1 2.5,19.06 ; J25.1 v1(1.48,20) 1.39,20 ; J25.1 2.5,21.02
  L3_SIGNAL w0.508: J25.1 2.5,21.01 ; J25.1 2.5,19.12 ; J25.1 v1(1.48,20)
  L4_GND2 w0.508: J25.1 2.5,21.11 ; J25.1 v1(1.48,20) 1.36,20 ; J25.1 2.5,19.06
  L5_POWER w0.508: J25.1 2.5,21.04 ; J25.1 2.5,19.15 ; J25.1 v1(1.48,20) 1.42,20
  BOTTOM w0.127: 44.77,23.74 44.65,23.85 41.83,23.85 41.68,23.7
  BOTTOM w0.3: U13.4 v1(56.39,18.9)
  BOTTOM w0.508: 1.45,20 v1(1.48,20) J25.1 ; J25.1 2.5,19.1 ; J25.1 2.5,20.93
  vias: v1(0.51,34.06) v1(0.51,32.79) v1(0.52,28.03) v1(0.52,25.77) v1(0.51,23.9) v1(0.52,22.45) v1(0.51,20.83) v1(0.5,18.53) v1(0.51,16.24) v1(0.55,14.07) v1(0.55,10.73) v1(0.51,7.57) v1(0.51,5.52) v1(0.51,3.16) v1(0.53,0.52) v1(1.49,19.39) v1(1.71,34.07) v1(1.78,31.67) v1(1.83,23.09) v1(1.91,29.6) v1(1.91,26.86) v1(1.88,24.33) v1(2.18,19.08) v1(2.3,21.83) v1(2.34,15.29) v1(2.44,33.55) v1(2.36,12.83) v1(2.39,9.14) v1(2.37,6.95) v1(2.48,32.59) v1(2.51,21.04) v1(2.54,17.68) v1(2.57,16.5) v1(2.6,4.13) v1(2.79,34.26) v1(2.92,19.06) v1(3.15,27.85) v1(3.14,22.9) v1(3.19,30.86) v1(3.19,29.84) v1(3.31,5.6) v1(3.38,34.25) v1(3.4,25.83) v1(3.37,11.2) v1(3.51,1.93) v1(3.61,21.03) v1(3.85,0.53) v1(3.92,28.44) v1(3.86,23.98) v1(3.94,21.96) v1(3.92,15.71) v1(3.99,31.84) v1(4.17,33.55) v1(4.32,19.11) v1(4.31,14.59) v1(4.36,29.62) v1(4.45,25.11) v1(4.42,22.4) v1(4.39,7.4) v1(4.78,34.24) v1(4.89,27.97) v1(4.89,27.41) v1(4.86,23.93) v1(4.91,12.28) v1(4.9,9.63) v1(4.98,16.54) v1(5.18,1.93) v1(5.27,31.53) v1(5.52,18.31) v1(5.98,5.64) v1(5.99,4.43) v1(6.17,32.58) v1(6.43,22.19) v1(6.49,34.24) v1(6.48,14.78) v1(6.55,21.31) v1(6.74,30.1) v1(6.74,29.57) v1(6.69,7.34) v1(6.69,6.77) v1(7.01,21.87) v1(7.05,14.77) v1(7.02,3.29) v1(7.14,33.57) v1(7.07,12.19) v1(7.16,31.52) v1(7.33,28.37) v1(7.26,0.52) v1(7.52,17.45) v1(7.63,27.39) v1(7.7,19.11) v1(7.73,8.84) v1(7.76,23.79) v1(7.79,9.82) v1(7.89,29.72) v1(7.89,7.66) v1(7.99,21.34) v1(7.96,11.65) v1(8.01,10.35) v1(8.14,34.21) v1(8.24,15.14) v1(8.15,12.81) v1(8.24,9.37) v1(8.28,5.64) v1(8.26,4.45) v1(8.33,3.09) v1(8.55,26.76) v1(8.6,24.6) v1(8.65,12.1) v1(8.7,34.21) v1(8.83,19.19) v1(8.84,1.88) v1(8.85,21.96) v1(8.89,15.14) v1(8.99,17.58) v1(9.02,9.99) v1(9.08,25.03) v1(9.21,9.04) v1(9.27,31.42) v1(9.33,26.57) v1(9.49,11.81) v1(9.56,33.58) v1(9.68,10.33) v1(9.78,0.51) v1(9.87,13.06) v1(9.98,14.41) v1(10.12,4.43) v1(10.2,32.63) v1(10.16,22.75) v1(10.21,3.26) v1(10.3,29.74) v1(10.34,7.58) v1(10.29,5.69) v1(10.35,17.23) v1(10.44,1.88) v1(10.54,34.24) v1(10.45,19.98) v1(10.49,17.86) v1(10.6,27.99) v1(10.97,19.35) v1(11.02,17.35) v1(11.04,13.36) v1(11.2,26.62) v1(11.18,24.24) v1(11.35,22.73) v1(11.51,9.21) v1(11.63,33.58) v1(11.57,18.8) v1(11.61,17.35) v1(11.93,31.43) v1(12,5.77) v1(12.01,4.43) v1(12.05,25.2) v1(12.19,0.51) v1(12.34,29.57) v1(12.37,3.25) v1(12.46,26.64) v1(12.61,34.23) v1(12.59,8.72) v1(12.97,7.43) v1(13.14,32.6) v1(13.13,28.52) v1(13.35,18.46) v1(13.36,20.25) v1(13.51,15.58) v1(13.83,8.88) v1(13.93,19.35) v1(14.01,6.16) v1(14.11,2.03) v1(14.11,0.51) v1(14.19,31.51) v1(14.54,14.39) v1(14.63,34.23) v1(14.63,26.63) v1(14.59,11.49) v1(14.73,20.25) v1(14.73,18.49) v1(14.67,5.12) v1(14.81,23.25) v1(14.76,15.54) v1(14.88,12.73) v1(14.87,8.65) v1(14.86,7.01) v1(15.1,32.5) v1(15.21,34.23) v1(15.15,30.58) v1(15.24,24.04) v1(15.34,3.45) v1(15.4,19.35) v1(15.68,9.39) v1(15.91,0.52) v1(15.96,31.33) v1(16.03,18.5) v1(16.07,27.43) v1(16.1,20.26) v1(16.05,15.81) v1(16.12,12.94) v1(16.1,11.87) v1(16.19,14.11) v1(16.54,8.69) v1(16.56,7.1) v1(16.65,2.37) v1(16.66,4.58) v1(17.01,30.52) v1(16.98,28.51) v1(16.98,26.4) v1(16.97,24.87) v1(17.25,32.6) v1(17.27,14.71) v1(17.27,13.2) v1(17.27,11.87) v1(17.49,34.33) v1(17.46,22.15) v1(17.58,0.53) v1(18,31.48) v1(17.97,27.39) v1(18.24,35.28) v1(18.39,25.95) v1(18.4,24.78) v1(18.41,23.41) v1(18.35,15.86) v1(18.4,5.87) v1(18.47,21.41) v1(18.45,11.87) v1(18.49,6.91) v1(18.58,18.41) v1(18.71,32.93) v1(18.77,34.3) v1(18.82,30.25) v1(18.83,28.37) v1(18.83,12.41) v1(18.77,4.19) v1(18.9,10.25) v1(18.94,8.37) v1(18.96,5.85) v1(19.14,0.52) v1(19.24,33.11) v1(19.3,23.65) v1(19.3,9.84) v1(19.39,14.78) v1(19.38,13.09) v1(19.48,20.37) v1(19.48,18.82) v1(19.46,11.35) v1(19.56,22.45) v1(19.68,4.01) v1(19.79,3.21) v1(20.12,6.64) v1(20.17,35.27) v1(20.19,34.34) v1(20.45,30.07) v1(20.43,28.49) v1(20.52,31.65) v1(20.5,4.04) v1(20.5,3.12) v1(20.94,10.76) v1(20.98,34.44) v1(21.07,27.04) v1(21.08,24.17) v1(21.23,22.72) v1(21.23,20.5) v1(21.54,24.88) v1(21.5,16.71) v1(21.48,14.9) v1(21.46,12.78) v1(21.62,31.79) v1(21.64,29.17) v1(21.63,27.67) v1(21.74,35.15) v1(21.73,34.48) v1(21.67,33.13) v1(21.72,26.29) v1(21.74,9.94) v1(21.81,25.68) v1(21.93,5.63) v1(21.93,3.92) v1(22.14,8.69) v1(22.3,12.23) v1(22.31,6.82) v1(22.39,0.53) v1(22.62,22.82) v1(22.62,16.89) v1(22.64,15.68) v1(22.66,24.43) v1(22.72,18.69) v1(23.1,35.14) v1(23.18,23.94) v1(23.34,33.1) v1(23.34,27.04) v1(23.27,23.04) v1(23.37,30.21) v1(23.51,17.27) v1(23.53,14.33) v1(23.46,11.94) v1(23.51,1.66) v1(23.6,34.32) v1(23.83,28.24) v1(23.76,20.28) v1(23.98,26) v1(24.03,18.71) v1(24.13,15.38) v1(24.1,0.5) v1(24.31,31.74) v1(24.33,29.22) v1(24.41,34.32) v1(24.37,20.28) v1(24.38,12.2) v1(24.71,16.66) v1(24.66,5.91) v1(24.71,4.14) v1(24.71,3.28) v1(24.73,2.41) v1(24.71,1.57) v1(24.75,26.29) v1(24.8,7) v1(24.92,24.4) v1(25.08,22.75) v1(25.2,34.32) v1(25.27,30.19) v1(25.29,27.6) v1(25.34,26.29) v1(25.34,18.72) v1(25.35,15.53) v1(25.32,14.19) v1(25.46,33.07) v1(25.49,24.4) v1(25.48,12.2) v1(25.78,20.49) v1(25.76,4.45) v1(25.86,5.91) v1(26.02,34.33) v1(25.96,31.09) v1(25.96,29.14) v1(26.01,23.81) v1(26.01,23.14) v1(25.97,10.21) v1(26.15,22.3) v1(26.14,21.02) v1(26.16,21.67) v1(26.44,15.24) v1(26.7,31.09) v1(26.67,29.12) v1(26.66,10.27) v1(26.8,34.32) v1(27.04,23.53) v1(26.99,21.77) v1(27.1,7) v1(27.18,0.46) v1(27.3,26.21) v1(27.42,31.08) v1(27.42,30.43) v1(27.43,29.79) v1(27.42,29.12) v1(27.42,28.27) v1(27.42,27.69) v1(27.36,10.27) v1(27.37,2.86) v1(27.55,18.83) v1(27.52,5.91) v1(27.52,4.1) v1(27.61,34.32) v1(27.67,17.42) v1(27.67,6.99) v1(27.79,3.38) v1(27.89,10.27) v1(28.02,22.8) v1(28.07,31.09) v1(28.11,29.12) v1(28.27,33.07) v1(28.32,24.37) v1(28.41,34.32) v1(28.74,31.09) v1(28.78,29.12) v1(28.8,3.37) v1(28.85,20.12) v1(29.01,6.91) v1(28.97,4.42) v1(29.1,15.57) v1(29.2,34.33) v1(29.21,9.26) v1(29.16,3.85) v1(29.38,31.09) v1(29.38,30.44) v1(29.38,29.77) v1(29.39,29.12) v1(29.4,28.26) v1(29.39,27.61) v1(29.62,17.58) v1(29.73,33.06) v1(29.72,11.37) v1(29.67,7.48) v1(29.84,1.56) v1(29.95,26.42) v1(30,34.32) v1(30.04,31.08) v1(30.01,18.83) v1(30.06,0.46) v1(30.28,20.19) v1(30.52,29.11) v1(30.52,2.95) v1(30.8,34.33) v1(30.84,22.03) v1(30.89,31.08) v1(30.96,23.03) v1(31.09,29.12) v1(31.13,1.56) v1(31.19,16.98) v1(31.18,16.26) v1(31.29,21.02) v1(31.42,33.06) v1(31.38,27.8) v1(31.36,12.53) v1(31.53,31.06) v1(31.48,20.09) v1(31.6,34.33) v1(31.75,29.84) v1(32.07,22.01) v1(32.3,20.12) v1(32.31,12.04) v1(32.26,0.47) v1(32.4,34.33) v1(32.37,32.64) v1(32.41,17.6) v1(32.36,14.78) v1(32.55,21.09) v1(32.87,31.04) v1(32.93,24.09) v1(32.93,14.78) v1(32.89,12.04) v1(32.96,17.6) v1(33.1,29.57) v1(33.1,9.13) v1(33.17,34.33) v1(33.22,4.44) v1(33.29,23.22) v1(33.32,21.87) v1(33.34,6.38) v1(33.3,5.42) v1(33.36,33.1) v1(33.43,17.32) v1(33.69,35.17) v1(33.95,16.59) v1(33.93,15.27) v1(33.93,14.72) v1(34.02,19.88) v1(33.96,17.32) v1(33.96,13.84) v1(33.97,13.13) v1(33.99,11.65) v1(33.99,10.73) v1(34.01,9.14) v1(34.07,20.65) v1(34.21,21.86) v1(34.26,22.83) v1(34.54,24.51) v1(34.47,4.52) v1(34.61,11.99) v1(35.04,35.15) v1(35.13,29.13) v1(35.2,34.37) v1(35.15,33.11) v1(35.17,31.03) v1(35.19,27.7) v1(35.17,14.68) v1(35.26,36.11) v1(35.33,17.61) v1(35.26,11.99) v1(35.55,37.11) v1(35.57,19.05) v1(35.74,26.06) v1(35.74,24.78) v1(35.7,22.61) v1(35.75,30.07) v1(35.75,23.81) v1(35.81,20.41) v1(35.75,14.67) v1(35.78,9.08) v1(35.93,11.98) v1(35.98,39.9) v1(35.95,17.35) v1(36.32,19.46) v1(36.32,9.08) v1(36.33,5.18) v1(36.35,4.14) v1(36.53,33.07) v1(36.47,31.18) v1(36.54,27.13) v1(36.51,6.17) v1(36.63,16.8) v1(36.61,15.43) v1(36.6,14.01) v1(36.6,13.42) v1(36.68,42.46) v1(36.73,37.88) v1(36.74,17.48) v1(36.69,10.93) v1(36.93,34.32) v1(36.93,22.77) v1(36.97,24.75) v1(37.02,6.49) v1(37.01,4.28) v1(36.96,3.52) v1(37.08,36.2) v1(37.13,4.98) v1(37.25,20.82) v1(37.33,21.96) v1(37.33,17.48) v1(37.34,7) v1(37.48,9.07) v1(37.6,31.22) v1(37.69,39.22) v1(37.69,14.67) v1(37.74,3.31) v1(37.82,11.98) v1(38.14,41.62) v1(38.18,35.29) v1(38.15,33.1) v1(38.18,27.06) v1(38.42,23.09) v1(38.38,14.68) v1(38.53,29.13) v1(38.49,11.98) v1(38.53,3.31) v1(38.58,32.12) v1(38.65,24.54) v1(38.63,19.44) v1(38.68,42.24) v1(38.7,35.84) v1(38.71,21.53) v1(38.91,37.68) v1(38.91,31.11) v1(39.03,29.65) v1(38.96,19.85) v1(39,14.68) v1(39.08,39.67) v1(39.09,6.67) v1(39.28,22.48) v1(39.31,17.06) v1(39.43,10.85) v1(39.54,15.38) v1(39.54,14.68) v1(39.55,13.83) v1(39.54,13.04) v1(39.64,24.28) v1(39.57,16.59) v1(39.59,12.32) v1(39.71,6.68) v1(39.84,35.62) v1(39.97,30.14) v1(40.13,36.25) v1(40.09,34.71) v1(40.17,33.95) v1(40.21,32.25) v1(40.2,6.22) v1(40.2,5.6) v1(40.2,3.33) v1(40.37,21.6) v1(40.49,22.78) v1(40.47,6.78) v1(40.49,5.02) v1(40.6,42.51) v1(40.84,7.26) v1(40.87,39.12) v1(40.93,3.63) v1(40.98,4.48) v1(41.06,31.33) v1(41.11,29.79) v1(41.22,5.94) v1(41.35,22.92) v1(41.44,8.52) v1(41.53,18.07) v1(41.53,6.86) v1(41.61,37.45) v1(41.58,24.75) v1(41.58,12.97) v1(41.64,3.35) v1(41.74,16.43) v1(41.83,36.23) v1(41.82,33.97) v1(41.87,35.6) v1(41.87,34.71) v1(41.95,26.61) v1(41.9,21.6) v1(41.87,19.44) v1(42,32.16) v1(42.02,30.43) v1(41.99,28.52) v1(42.09,24.75) v1(42.11,8.99) v1(42.09,5.36) v1(42.21,29.74) v1(42.19,13.98) v1(42.23,12.33) v1(42.42,26.59) v1(42.43,19.7) v1(42.39,6.92) v1(42.48,28.52) v1(42.46,4.38) v1(42.56,31.48) v1(42.58,24.75) v1(42.56,10.15) v1(42.56,8.48) v1(42.82,36.96) v1(42.81,17.21) v1(42.8,9.19) v1(42.77,6.22) v1(42.94,32.17) v1(42.89,3.39) v1(42.98,39.24) v1(43.13,34.02) v1(43.19,42.51) v1(43.33,5.54) v1(43.41,34.65) v1(43.37,9.8) v1(43.74,28.97) v1(43.7,26.47) v1(43.69,13.2) v1(43.84,36.03) v1(43.85,41.38) v1(43.85,31.41) v1(43.92,4.45) v1(44.21,9.8) v1(44.4,38.53) v1(44.37,5.56) v1(44.53,30.24) v1(44.73,37.25) v1(44.77,34.68) v1(44.75,32.26) v1(44.81,25.78) v1(44.82,18.77) v1(44.83,17.93) v1(44.83,17.03) v1(44.84,16.1) v1(44.95,22.21) v1(44.88,10.15) v1(44.98,40.94) v1(45.01,26.35) v1(45.05,5.94) v1(45.15,20.78) v1(45.06,9.45) v1(45.16,7.95) v1(45.16,7.39) v1(45.31,13.17) v1(45.5,42.51) v1(45.59,31.39) v1(45.61,18.76) v1(45.59,17.93) v1(45.59,17.03) v1(45.61,16.12) v1(45.68,8.39) v1(45.67,7) v1(45.78,9.18) v1(45.77,6.22) v1(46.04,38.53) v1(46.09,41.34) v1(46.09,40.49) v1(46.1,34.79) v1(46.08,28.74) v1(46.23,36.41) v1(46.2,33.95) v1(46.19,24.75) v1(46.33,32.12) v1(46.3,13.82) v1(46.42,18.75) v1(46.42,17.93) v1(46.41,17.02) v1(46.41,16.12) v1(46.46,39.83) v1(46.49,37.22) v1(46.72,24.75) v1(46.75,10.12) v1(46.98,7.47) v1(47.07,42.47) v1(47.1,9.09) v1(47.31,38.27) v1(47.31,31.42) v1(47.29,30.25) v1(47.31,18.75) v1(47.31,17.93) v1(47.31,17.01) v1(47.29,16.1) v1(47.47,13.2) v1(47.57,39.09) v1(47.61,23.43) v1(47.62,22.75) v1(47.8,33.96) v1(47.79,32.21) v1(47.92,35.83) v1(47.88,34.76) v1(48.13,24.75) v1(48.15,18.62) v1(48.13,17.91) v1(48.15,16.09) v1(48.16,16.98) v1(48.23,1.35) v1(48.33,42.49) v1(48.31,15.47) v1(48.27,13.89) v1(48.31,10.27) v1(48.26,8.79) v1(48.37,39.09) v1(48.62,35.1) v1(48.6,28.96) v1(48.56,27.15) v1(48.84,34.05) v1(48.83,32.14) v1(48.83,30.38) v1(49.12,39.09) v1(49.14,0.48) v1(49.17,21.81) v1(49.5,42.46) v1(49.68,36.64) v1(49.75,24.26) v1(49.78,2.9) v1(49.91,24.75) v1(49.91,22.94) v1(50.13,39.8) v1(50.05,27.53) v1(50.09,20.89) v1(50.16,34.04) v1(50.2,32.27) v1(50.44,37.83) v1(50.36,35) v1(50.51,41.21) v1(50.51,40.45) v1(50.71,34.02) v1(50.94,31.19) v1(51.04,31.97) v1(51,26.59) v1(50.99,23.08) v1(51.07,42.49) v1(51.1,1.44) v1(51.41,36.12) v1(51.41,24.79) v1(51.6,33.72) v1(51.7,32.56) v1(51.65,4.78) v1(51.85,31.22) v1(51.88,3.02) v1(51.99,40.51) v1(52.02,39) v1(52.13,37.43) v1(52.11,19.81) v1(52.16,42.23) v1(52.24,23.15) v1(52.35,25.72) v1(52.46,24.57) v1(52.74,31.22) v1(52.69,18.87) v1(52.7,16.28) v1(52.74,12.37) v1(52.77,40.94) v1(52.77,32.58) v1(52.78,14) v1(52.81,11.29) v1(52.88,36.31) v1(53.09,0.52) v1(53.17,39.22) v1(53.4,34.8) v1(53.37,24.3) v1(53.4,14.72) v1(53.44,6.55) v1(53.64,25.73) v1(53.71,31.94) v1(53.72,31.29) v1(53.66,29.02) v1(53.66,28.3) v1(54.06,36.49) v1(54.08,13.8) v1(54.05,8.76) v1(54.2,23.24) v1(54.24,18.9) v1(54.17,18.06) v1(54.2,5.5) v1(54.27,15.62) v1(54.31,10.5) v1(54.53,32.54) v1(54.58,7.94) v1(54.71,34.61) v1(54.95,25.72) v1(55.12,16.36) v1(55.21,13.22) v1(55.38,28.42) v1(55.37,18.08) v1(55.52,4.15) v1(55.47,1.97) v1(56.1,36.5) v1(56.24,31.6) v1(56.3,34.26) v1(56.53,16.26) v1(56.83,32.66) v1(56.83,32.11) v1(57.02,3.26) v1(57.11,25.7) v1(57.15,21.72) v1(57.09,0.52) v1(57.18,29.91) v1(57.24,11.42) v1(57.34,27.94) v1(57.32,17.27) v1(57.53,9.68) v1(57.65,35.52) v1(57.62,34.67) v1(57.75,32.63) v1(57.7,6.18) v1(57.78,25.31) v1(57.85,14.99) v1(57.85,14.35) v1(57.89,30.81) v1(57.92,29.01) v1(57.87,18.92) v1(58.19,23.71) v1(58.18,8.17) v1(58.34,36.47) v1(58.45,18.21) v1(58.42,13.31) v1(58.47,23.16) v1(58.53,15.9) v1(59.11,29.07) v1(59.11,28.27) v1(59.08,23.91) v1(59.09,11.16) v1(59.3,35.26) v1(59.36,32.8) v1(59.45,31.05) v1(59.7,23.93) v1(59.75,28.28) v1(59.91,6.16) v1(60.05,25.77) v1(60.02,18.22) v1(60.29,31.7) v1(60.55,13.3) v1(60.85,36.49) v1(60.83,33.24) v1(61.3,34.72) v1(61.35,10.68) v1(61.61,30.25) v1(61.57,27.9) v1(61.57,23.19) v1(61.67,29.08) v1(61.72,26.66) v1(61.66,25.18) v1(61.71,19.76) v1(61.66,14.99) v1(61.66,14.35) v1(61.79,17.27) v1(62.05,32.3) v1(62.05,21.77) v1(62.1,8.05) v1(62.28,13.63) v1(62.37,24.27) v1(63,27.89) v1(63,25.74) v1(63,25.18) v1(63.2,6.16) v1(63.33,15.86) v1(63.41,36.46) v1(63.45,34.53) v1(63.4,19.84) v1(63.55,30.95) v1(63.59,23.79) v1(63.69,22.53) v1(64.15,28.82) v1(64.38,31.71) v1(64.41,30.19) v1(64.57,34.77) v1(64.57,24.88) v1(64.66,25.46) v1(64.69,21.32) v1(64.66,17.78) v1(65.11,23.99) v1(65.18,30.94) v1(65.16,27.9) v1(66.03,36.46) v1(66.01,15.86) v1(66.04,6.15) v1(66.07,19.86) v1(66.15,22.73) v1(66.31,30.1) v1(66.29,27.27) v1(66.31,25.43) v1(66.87,8.19) v1(67.25,13.72) v1(67.3,21.37) v1(67.46,17.74) v1(67.63,33.87) v1(67.65,36.44) v1(68.22,31.55) v1(68.31,26.2) v1(68.35,30.04) v1(68.43,15.99) v1(68.43,12.85) v1(68.44,9.18) v1(68.48,28.14) v1(68.47,23.95) v1(68.45,19.94) v1(68.5,6.13)
VBAT: length 9.1
  BOTTOM w0.254: 9.23,20.81 9.23,20.81 R15.2
  BOTTOM w1: C168.2 10.17,21.76 8.4,19.98 Q6.3 7.27,20 J25.2
VCC_5V: length 106.8
  TOP w0.2: v1(18.33,8.43) 18.33,7.79 20.05,6.06 v1(20.21,6.06)
  TOP w0.508: v1(49.36,35.8) v1(49.91,35.8) 50.71,35.8 51.07,35.45 51.85,35.45 53.81,33.49 C161.1 55.37,33.49 C160.1 55.37,30 J22.1
  L5_POWER w0.381: v1(49.36,35.8) 49.42,35.75 49.42,30.21 52.35,27.28 65.27,27.28 v1(65.28,27.27)
  L5_POWER w0.508: v1(15.67,10.15) v1(15.1,10.15) 9.65,15.6 9.65,17.83 9.46,18.02 9.46,23.83 11.82,26.19 11.82,28.09 17.45,33.72 35.47,33.72 37.86,36.11 37.86,37.54 40.04,39.73 41.3,39.73 43.1,37.92 46.71,37.92 48.4,36.23 48.93,36.23 v1(49.36,35.8) v1(49.91,35.8)
  BOTTOM w0.2: R145.1 20.35,6.06 v1(20.21,6.06)
  BOTTOM w0.381: U16.1 65.28,26.4 C138.1 v1(65.28,27.27)
  vias: v1(12.21,10.21) v1(12.53,10.64)
BAT_ADC: length 36
  TOP w0.127: v1(22.39,8.06) 21.67,8.06 11.33,18.4 v1(10.36,18.4) ; U4.92 35.49,7.57 34.44,6.53 v1(34.44,5.91) 34.47,5.88 C172.1
  L3_SIGNAL w0.127: v1(34.44,5.91) 33.38,4.84 23.86,4.84 22.86,5.84 22.86,7.59 v1(22.39,8.06)
  BOTTOM w0.127: v1(10.36,18.4) R16.1 R15.1
BAT_CHRG: length 33.9
  L5_POWER w0.381: v1(4.1,2.02) 5.94,3.86 12.48,3.86 17.81,9.18 17.81,20.75 v1(15.36,23.19)
  BOTTOM w0.381: U20.7 v1(15.36,23.19) ; D25.2 4.1,2.25 v1(4.1,2.02)
BAT_STBY: length 31.8
  L5_POWER w0.381: v1(3.53,5) 12.08,5 16.73,9.65 16.73,20.56 v1(14.09,23.19)
  BOTTOM w0.381: U20.6 v1(14.09,23.19) ; D5.2 v1(3.53,5)
BUTTON_1: length 38
  TOP w0.127: v1(41.69,9.39) 41.38,9.39 41.11,9.66 40.24,9.66 U4.3
  L3_SIGNAL w0.127: v1(41.69,9.39) 41.42,9.39 41.01,9.8 33.2,9.8 31.33,7.94 25.91,7.94 22.73,11.11 22.73,13.06 v1(19.71,16.08)
  BOTTOM w0.127: v1(19.71,16.08) 19.64,16.08 19.05,16.68 19.05,22.6 R262.1 20.92,23.42 SW3.3
BUTTON_2: length 30.6
  TOP w0.127: v1(41.48,9.89) 41.35,10.02 U4.4
  L3_SIGNAL w0.127: v1(41.48,9.89) 41.45,9.92 41.36,9.92 41.22,10.06 33.07,10.06 31.2,8.19 26.06,8.19 23.06,11.19 23.06,13.89 19.96,16.99 v1(19.74,16.99)
  BOTTOM w0.127: SW4.3 20.92,17.43 R263.1 19.74,17.2 v1(19.74,16.99)
BUTTON_3: length 26.7
  TOP w0.127: U4.5 41.65,10.37 42.02,9.99 v1(42.02,9.86)
  L3_SIGNAL w0.127: v1(42.02,9.86) 42.02,9.96 41.66,10.33 32.97,10.33 31.09,8.45 26.21,8.45 23.7,10.96 v1(23.7,11.43)
  BOTTOM w0.127: R264.1 20.92,11.42 SW5.3 v1(23.7,11.43)
C6_BOOT: length 25.6
  TOP w0.127: v1(32.09,31.09) 32.4,30.78 U11.23 32.4,23.84 31.08,22.52 30.12,22.52 25.95,18.34 25.95,14.55 26.43,14.07 29.59,14.07 29.8,13.87 U4.64
  BOTTOM w0.127: v1(32.09,31.09) 32.09,31.61 TP45.1
C6_EN: length 68
  TOP w0.127: U4.10 40.56,12.12 40.78,11.9 v1(40.93,11.9) ; C111.1 R134.1 ; C111.1 20.54,27.96 20.54,19.55 v1(25.1,14.99) ; C111.1 22.5,28.5 U11.8 23.24,28.5 v1(23.44,28.7)
  L3_SIGNAL w0.127: v1(40.93,11.9) 40.93,11.62 41.36,11.19 43.92,11.19 45.73,13 45.73,13.8 44.41,15.13 44.41,20.28 42.66,22.03 39.79,22.03 37.63,19.88 34.62,19.88 33.4,18.66 31.41,18.66 30.58,17.83 30.58,16.46 28.71,14.59 27.71,14.59 26.9,13.78 26.3,13.78 v1(25.1,14.99)
  BOTTOM w0.127: TP44.1 30.47,29.63 29.54,28.7 v1(23.44,28.7)
C6_IO0: length 1.2
  TOP w0.127: U11.12 23.6,24.17 R298.1
C6_IO1: length 1.1
  TOP w0.127: R299.1 24.4,24.14 U11.13
C6_IO8: length 1.3
  TOP w0.127: U11.22 31.6,23.94 R135.1
C6_U0RXD: length 34.1
  TOP w0.127: U11.30 33.62,30.1 v1(33.54,30.18) ; v1(27.5,13.07) 27.53,13.03 28.59,13.03 R300.2
  BOTTOM w0.127: v1(27.5,13.07) 27.37,12.94 24.07,12.94 22.21,14.8 22.21,20.56 21.92,20.85 21.92,22.4 22.21,22.7 22.21,24.85 24.18,26.82 29.77,26.82 33.12,30.18 v1(33.54,30.18) 34.28,30.91 TP46.1
